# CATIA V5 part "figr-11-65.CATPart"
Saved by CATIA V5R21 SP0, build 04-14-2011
Part number: Part1
Bounding box of the stored display mesh (mm): x -54 to 54, y -91.936 to 93.838, z -12.649 to 110.643
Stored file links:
  D:\CATIA V5R21 E-RESOURCES\CATIA-V5R21\catia-v5r21-prt\c11-catia-v5r21-prt\c11-catia-v5r21-figr-11-65.CATPart
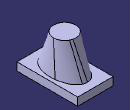
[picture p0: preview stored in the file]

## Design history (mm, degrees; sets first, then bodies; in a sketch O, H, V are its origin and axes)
Set1
  Loft1: Sections (Sketch4; Sketch3)
Body1 (main body)
  Sketch1 on yz-plane, origin (0, 0, 0), H (0, 1, 0), V (0, 0, 1)
    point P1 (93.8379, 11.643)
    line L1 (93.8379, 11.643) -> (93.8379, -12.6487)
    line L2 (93.8379, -12.6487) -> (-91.9362, -12.6487)
    line L3 (-91.9362, -12.6487) -> (-91.9362, 11.643)
    line L4 (-91.9362, 11.643) -> (93.8379, 11.643)
    point P5 (93.8379, 11.643)
    vertical: L1 V, L3 V
    horizontal: L2 H, L4 H
    coincidence: P5 P1
  Pad1: profile Sketch1, direction (1, 0, 0), length 54, mirrored extent
  Sketch2 on face of Pad1, origin (0, 0, 11.643), H (1, 0, 0), V (0, 1, 0)
    circle A1 centre (0, 0) radius 16.7533
    point P1 (16.7533, 0)
    coincidence: A1 P1, P1 H
  Pad2: profile Sketch2, direction (0, 0, 1), length 99
  SewSurface1: SewingRemoveFace face of Pad2, SplitPlane Loft1
  Sketch3 on face of Pad2, origin (0, 0, 110.643), H (1, 0, 0), V (0, 1, 0)
    point P1 (0, 42.8937)
    point P2 (33.9651, 0)
    projected circle E1 centre (0, 0) radius 16.7533 from edge [face of Pad2 | face of Pad2]
    circle A1 centre (0, 0) radius 33.9651
    point P3 (0, 33.9651)
    coincidence: P1 V, P2 H, A1 P2, A1 P3, P3 V
  Sketch4 on face of Pad1, origin (0, 0, 11.643), H (1, 0, 0), V (0, 1, 0)
    ellipse A1 centre (0, 0) semi-axes 69.9141, 43.1918 rotation 90
    point P1 (0, 69.9141)
    point P2 (43.1918, 0)
    coincidence: P1 V, P2 H, A1 P1, A1 P2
